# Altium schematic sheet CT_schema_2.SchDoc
size 313 x 185 mm
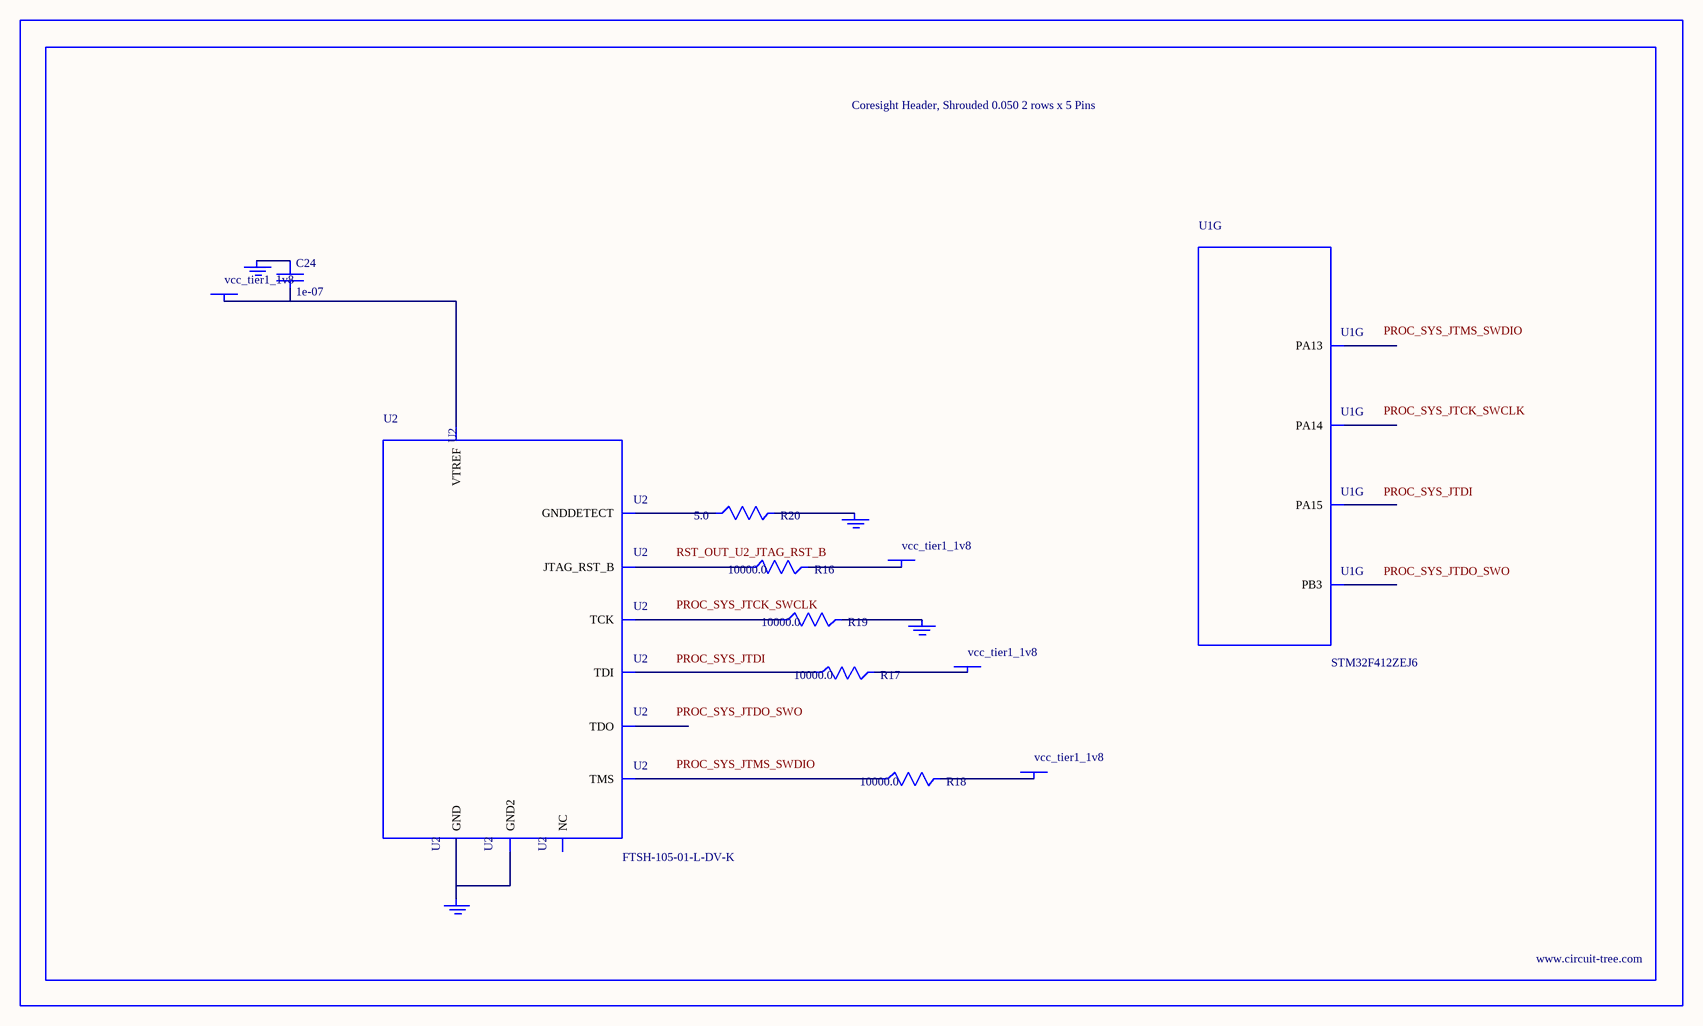
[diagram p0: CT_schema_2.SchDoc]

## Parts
BORDER1  (no value)
C24  1e-07  [C0402]
GND_INSTANCE_1_0  (no value)
GND_INSTANCE_1_1  (no value)
GND_INSTANCE_1_2  (no value)
GND_INSTANCE_1_3  (no value)
POWER_INSTANCE_1_0  vcc_tier1_1v8
POWER_INSTANCE_1_1  vcc_tier1_1v8
POWER_INSTANCE_1_2  vcc_tier1_1v8
POWER_INSTANCE_1_3  vcc_tier1_1v8
R16  10000.0  [R0603]
R17  10000.0  [R0603]
R18  10000.0  [R0603]
R19  10000.0  [R0603]
R20  5.0  [R0603]
U1  STM32F412ZEJ6  [UFBGA144]  (part G of 11)
U2  FTSH-105-01-L-DV-K  [SAMTEC_FTSH-105-01-L-DV-K]

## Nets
NetC24_1: C24.1 GND_INSTANCE_1_0.0(GND)
NetC24_2: C24.2 POWER_INSTANCE_1_0.0(PWR) U2.1(VTREF)
NetGND_INSTANCE_1_1_0: GND_INSTANCE_1_1.0(GND) R19.2
NetGND_INSTANCE_1_2_0: GND_INSTANCE_1_2.0(GND) R20.2
NetGND_INSTANCE_1_3_0: GND_INSTANCE_1_3.0(GND) U2.3(GND) U2.5(GND2)
NetPOWER_INSTANCE_1_1_0: POWER_INSTANCE_1_1.0(PWR) R18.2
NetPOWER_INSTANCE_1_2_0: POWER_INSTANCE_1_2.0(PWR) R17.2
NetPOWER_INSTANCE_1_3_0: POWER_INSTANCE_1_3.0(PWR) R16.2
NetR16_1: R16.1 U2.10(JTAG_RST_B)
NetR17_1: R17.1 U2.8(TDI)
NetR18_1: R18.1 U2.2(TMS)
NetR19_1: R19.1 U2.4(TCK)
NetR20_1: R20.1 U2.9(GNDDETECT)

Not connected (* = marked no-connect by the designer): U1 A7(PB3) A10(PA15) A11(PA14) A12(PA13); U2 6(TDO) 7(NC)

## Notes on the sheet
- Labels drawn without touching a wire or pin: PROC_SYS_JTCK_SWCLK, PROC_SYS_JTDI, PROC_SYS_JTDO_SWO, PROC_SYS_JTMS_SWDIO, RST_OUT_U2_JTAG_RST_B

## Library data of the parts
BORDER1 = BORDER_PAGE1
C24 = C0402C104K3RACTU
GND_INSTANCE_1_0-GND_INSTANCE_1_3 = GND
POWER_INSTANCE_1_0-POWER_INSTANCE_1_3 = PWR
R16-R19 = RC0603JR-0710KL
R20 = ERJ-3GEYJ5R1V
